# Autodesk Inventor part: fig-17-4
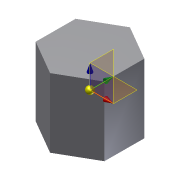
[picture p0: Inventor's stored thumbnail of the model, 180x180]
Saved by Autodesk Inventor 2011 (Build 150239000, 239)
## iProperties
Created: 2008-06
Part Number: fig-17-4
Document SubType Name: Modeling
Designer: CADCIM
Mass: 866.025 g
Surface Area: 519.615 cm^2
Volume: 866.025 cm^3
Density: 1 g/cm^3
Author: CADCIM
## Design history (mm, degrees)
sketch "Sketch1"
  geometry: L1 (0.184, 57.735)-(50.092, 28.708); L2 (50.092, 28.708)-(49.908, -29.027); L3 (49.908, -29.027)-(-0.184, -57.735); L4 (-0.184, -57.735)-(-50.092, -28.708); L5 (-50.092, -28.708)-(-49.908, 29.027); L6 (-49.908, 29.027)-(0.184, 57.735); 1 further point
  constraints: 12 end point, 13 other
  dimensions: "d0" = 100 distance between parallel lines of L2 L5
extrude "Extrusion1" new body sketch "Sketch1" distance "d1" = 100; taper "d2" = 0 deg
body "Solid1"
